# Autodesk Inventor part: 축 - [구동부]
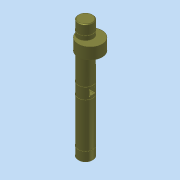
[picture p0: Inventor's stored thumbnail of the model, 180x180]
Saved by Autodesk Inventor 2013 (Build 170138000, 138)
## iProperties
Company: 한국ATC센터
Created: 2015-04
Part Number: 축 - [구동부]
Document SubType Name: Modeling
Designer: KYOUNG IL JANG
Density: 7.85 g/cm^3
Material: 강철
Mass: 606.905 g
Surface Area: 163.755 cm^2
Volume: 77.3127 cm^3
Author: KYOUNG IL JANG
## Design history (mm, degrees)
sketch "스케치1"
  geometry: C1 r 11 at (0, 0); 1 further point
  constraints: 1 centre point, 1 coincident
  dimensions: "d0" = 22 diameter of C1
extrude "돌출1" new body sketch "스케치1" stored distance "d1" = 180; taper "d2" = 0 deg
sketch "스케치2"
  geometry: L1 (-10.247, -4)-(10.247, -4); L2 (-10.247, 4)-(10.247, 4); A1 r 11 centre (0, 0) between (-10.247, -4) and (10.247, -4) reference; 1 further point
  constraints: 4 end point, 4 point on circle, 2 parallel, 1 horizontal
  dimensions: "d3" = 8 distance between parallel lines of L2 L1
extrude "돌출2" cut sketch "스케치2" stored distance "d4" = 8; taper "d5" = 0 deg
sketch "스케치3"
  geometry: 5 further points
hole "구멍1" sketch "스케치3" at (-4, 4), (4, 4), (4, -4), (-4, -4) diameter "d6" = 2; stored, may be unused: countersink angle "d10" = 90 deg, drill point angle "d12" = 118 deg; dims "d7" = 6, "d8" = 4, "d9" = 2, "d11" = 8
chamfer "모따기1" distance "d13" = 1; stored, may be unused: second distance "d14" = 2, angle "d15" = 45 deg
sketch "스케치4"
  geometry: L1 (-10, 9)-(-11, 9); L2 (-11, 9)-(-11, 7.8); L3 (-11, 7.8)-(-10, 7.8); L4 (-10, 7.8)-(-10, 9); L5 (-10, 90)-(10, 90) reference; L6 (0, -15)-(0, 90) reference; L7 (-10, 74.8)-(-11, 74.8); L8 (-11, 74.8)-(-11, 76); L9 (-11, 76)-(-10, 76); L10 (-10, 76)-(-10, 74.8); 1 further point
  constraints: 16 end point, 4 parallel, 2 equal length, 2 horizontal, 2 perpendicular, 1 collinear
  dimensions: "d16" = 7.8 distance from line of L3 point (0, 0); "d17" = 82.2 distance between parallel lines of L3 L5 (derived); "d18" = 11 distance from line of point (0, 0) L2; "d19" = 1 distance of L2.end L3.end; "d20" = 1.2 distance of L1.end L2.end; "d27" = 14 distance between parallel lines of L5 L9
revolve "회전1" sketch "스케치4" stored, may be unused: angle "d21" = 90 deg
sketch "스케치5"
  geometry: L1 (11, 52)-(-7, 52); L2 (-7, 52)-(-7, 69); L3 (-7, 69)-(11, 69); L4 (11, 69)-(11, 52); 1 further point
  constraints: 8 end point, 2 parallel, 1 horizontal, 1 perpendicular
  dimensions: "d22" = 17 distance of L3.end L1.start; "d23" = 36 diameter of L4 L2; "d24" = 7 horizontal distance of L2.end point (0, 0); "d25" = 52 distance from line of L1 point (0, 0)
revolve "회전2" sketch "스케치5" stored, may be unused: angle "d26" = 90 deg
node "솔리드1"
mirror "대칭1"
mirror "대칭2"
